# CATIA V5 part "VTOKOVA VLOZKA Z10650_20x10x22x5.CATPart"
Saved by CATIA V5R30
Part number: VTOKOVA VLOZKA Z10650/20x10x22x5
Bounding box of the stored display mesh (mm): x -10 to 10, y -5 to 5, z -22 to 0
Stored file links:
  C:\Users\ondra\Desktop\PŘÍLOHA P III\CATIA\VTOKOVA VLOZKA Z10650_20x10x22x5.CATPart
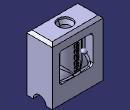
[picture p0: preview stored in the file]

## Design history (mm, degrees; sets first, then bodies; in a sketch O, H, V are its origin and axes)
Set1
  DatumSurface1 to DatumSurface308 "Z10650/2"
  Plane1: type Offset, RefPlane xy-plane, Offset 22, reversed
  Plane2: type Offset, RefPlane xy-plane, Offset 26
  Join1: Elements (DatumSurface1; DatumSurface2; DatumSurface3; DatumSurface4; DatumSurface5; DatumSurface6; DatumSurface7; DatumSurface8; DatumSurface9; DatumSurface10; DatumSurface11; DatumSurface12; DatumSurface13; DatumSurface14; DatumSurface15; DatumSurface16; DatumSurface17; DatumSurface18; DatumSurface19; DatumSurface20; DatumSurface21; DatumSurface22; DatumSurface23; DatumSurface24; DatumSurface25; DatumSurface26; DatumSurface27; DatumSurface28; DatumSurface29; DatumSurface30; DatumSurface31; DatumSurface32; DatumSurface33; DatumSurface34; DatumSurface35; DatumSurface36; DatumSurface37; DatumSurface38; DatumSurface39; DatumSurface40; DatumSurface41; DatumSurface42; DatumSurface43; DatumSurface44; DatumSurface45; DatumSurface46; DatumSurface47; DatumSurface48; DatumSurface49; DatumSurface50; DatumSurface51; DatumSurface52; DatumSurface53; DatumSurface54; DatumSurface55; DatumSurface56; DatumSurface57; DatumSurface58; DatumSurface59; DatumSurface60; DatumSurface61; DatumSurface62; DatumSurface63; DatumSurface64; DatumSurface65; DatumSurface66; DatumSurface67; DatumSurface68; DatumSurface69; DatumSurface70; DatumSurface71; DatumSurface72; DatumSurface73; DatumSurface74; DatumSurface75; DatumSurface76; DatumSurface77; DatumSurface78; DatumSurface79; DatumSurface80; DatumSurface81; DatumSurface82; DatumSurface83; DatumSurface84; DatumSurface85; DatumSurface86; DatumSurface87; DatumSurface88; DatumSurface89; DatumSurface90; DatumSurface91; DatumSurface92; DatumSurface93; DatumSurface94; DatumSurface95; DatumSurface96; DatumSurface97; DatumSurface98; DatumSurface99; DatumSurface100; DatumSurface101; DatumSurface102; DatumSurface103; DatumSurface104; DatumSurface105; DatumSurface106; DatumSurface107; DatumSurface108; DatumSurface109; DatumSurface110; DatumSurface111; DatumSurface112; DatumSurface113; DatumSurface114; DatumSurface115; DatumSurface116; DatumSurface117; DatumSurface118; DatumSurface119; DatumSurface120; DatumSurface121; DatumSurface122; DatumSurface123; DatumSurface124; DatumSurface125; DatumSurface126; DatumSurface127; DatumSurface128; DatumSurface129; DatumSurface130; DatumSurface131; DatumSurface132; DatumSurface133; DatumSurface134; DatumSurface135; DatumSurface136; DatumSurface137; DatumSurface138; DatumSurface139; DatumSurface140; DatumSurface141; DatumSurface142; DatumSurface143; DatumSurface144; DatumSurface145; DatumSurface146; DatumSurface147; DatumSurface148; DatumSurface149; DatumSurface150; DatumSurface151; DatumSurface152; DatumSurface153; DatumSurface154; DatumSurface155; DatumSurface156; DatumSurface157; DatumSurface158; DatumSurface159; DatumSurface160; DatumSurface161; DatumSurface162; DatumSurface163; DatumSurface164; DatumSurface165; DatumSurface166; DatumSurface167; DatumSurface168; DatumSurface169; DatumSurface170; DatumSurface171; DatumSurface172; DatumSurface173; DatumSurface174; DatumSurface175; DatumSurface176; DatumSurface177; DatumSurface178; DatumSurface179; DatumSurface180; DatumSurface181; DatumSurface182; DatumSurface183; DatumSurface184; DatumSurface185; DatumSurface186; DatumSurface187; DatumSurface188; DatumSurface189; DatumSurface190; DatumSurface191; DatumSurface192; DatumSurface193; DatumSurface194; DatumSurface195; DatumSurface196; DatumSurface197; DatumSurface198; DatumSurface199; DatumSurface200; DatumSurface201; DatumSurface202; DatumSurface203; DatumSurface204; DatumSurface205; DatumSurface206; DatumSurface207; DatumSurface208; DatumSurface209; DatumSurface210; DatumSurface211; DatumSurface212; DatumSurface213; DatumSurface214; DatumSurface215; DatumSurface216; DatumSurface217; DatumSurface218; DatumSurface219; DatumSurface220; DatumSurface221; DatumSurface222; DatumSurface223; DatumSurface224; DatumSurface225; DatumSurface226; DatumSurface227; DatumSurface228; DatumSurface229; DatumSurface230; DatumSurface231; DatumSurface232; DatumSurface233; DatumSurface234; DatumSurface235; DatumSurface236; DatumSurface237; DatumSurface238; DatumSurface239; DatumSurface240; DatumSurface241; DatumSurface242; DatumSurface243; DatumSurface244; DatumSurface245; DatumSurface246; DatumSurface247; DatumSurface248; DatumSurface249; DatumSurface250; DatumSurface251; DatumSurface252; DatumSurface253; DatumSurface254; DatumSurface255; DatumSurface256; DatumSurface257; DatumSurface258; DatumSurface259; DatumSurface260; DatumSurface261; DatumSurface262; DatumSurface263; DatumSurface264; DatumSurface265; DatumSurface266; DatumSurface267; DatumSurface268; DatumSurface269; DatumSurface270; DatumSurface271; DatumSurface272; DatumSurface273; DatumSurface274; DatumSurface275; DatumSurface276; DatumSurface277; DatumSurface278; DatumSurface279; DatumSurface280; DatumSurface281; DatumSurface282; DatumSurface283; DatumSurface284; DatumSurface285; DatumSurface286; DatumSurface287; DatumSurface288; DatumSurface289; DatumSurface290; DatumSurface291; DatumSurface292; DatumSurface293; DatumSurface294; DatumSurface295; DatumSurface296; DatumSurface297; DatumSurface298; DatumSurface299; DatumSurface300; DatumSurface301; DatumSurface302; DatumSurface303; DatumSurface304; DatumSurface305; DatumSurface306; DatumSurface307; DatumSurface308)
Body1 (main body)
  CloseSurface1: CloseElement Join1
  Sketch1 on Plane1, origin (0, 0, -22), H (1, 0, 0), V (0, 1, 0)
    circle A1 centre (-7.25, 0) radius 0.25
    point P1 (-7.25, 0)
    reference projected line E1 (-10, 5) -> (-10, -5) from edge [face of CloseSurface1 | face of CloseSurface1]
    radius A1 = 0.25
    distance E1 P1 = 2.75
    coincidence: P1 H
  Pocket1: profile Sketch1, direction (0, 0, -1), through (limit type 6)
